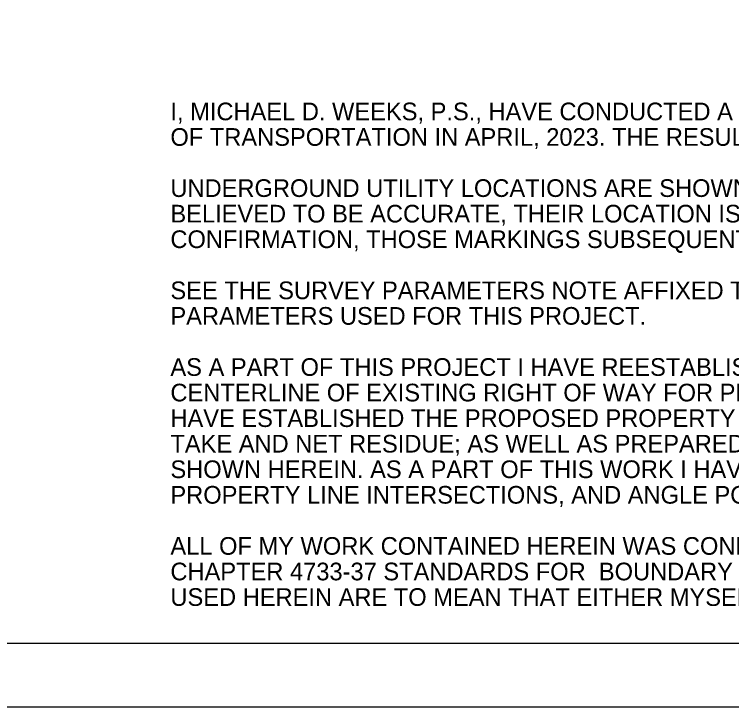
# Model space of a CAD drawing. Extents: x 0 to 34, y 0 to 22.
# Drawn here: x 16.3 to 21.98, y 0 to 5.49 of the extents above; entities that cross this region are included whole.
import ezdxf

# ---------------------------------------------------------------- set-up
doc = ezdxf.new("R2010")
doc.units = 0
for name, color, linetype in [('SH_Border', 7, 'Continuous'), ('SH_Cut_Line', 7, 'Continuous'), ('SH_Text', 7, 'Continuous')]:
    doc.layers.add(name, color=color, linetype=linetype)

msp = doc.modelspace()

# ---------------------------------------------------------------- linework, layer by layer
at = {"layer": 'SH_Border'}
msp.add_lwpolyline([(1.5, 21.5), (33.5, 21.5), (33.5, 0.5), (1.5, 0.5)], close=True, dxfattribs=at)
at = {"layer": 'SH_Cut_Line'}
msp.add_lwpolyline([(0, 0), (34, 0), (34, 22), (0, 22)], close=True, dxfattribs=at)

# ---------------------------------------------------------------- texts
at = {"layer": 'SH_Text'}
for s, p in [('I, MICHAEL D. WEEKS, P.S., HAVE CONDUCTED A SURVEY OF THE EXISTING CONDITIONS FOR THE OHIO DEPARTMENT ', (17.533, 4.646)), ('OF TRANSPORTATION IN APRIL, 2023. THE RESULTS OF THAT SURVEY ARE CONTAINED HEREIN.', (17.533, 4.4435)), ('UNDERGROUND UTILITY LOCATIONS ARE SHOWN FOR INFORMATIONAL PURPOSES ONLY. THOUGH THEY ARE ', (17.533, 4.0385)), ('BELIEVED TO BE ACCURATE, THEIR LOCATION IS AS MARKED ON THE GROUND BY THE UTILITY COMPANY PER OHIO811 ', (17.533, 3.836)), ('CONFIRMATION, THOSE MARKINGS SUBSEQUENTLY BEING SURVEYED AS A PART OF THIS PROJECT.', (17.533, 3.6335)), ('SEE THE SURVEY PARAMETERS NOTE AFFIXED TO THESE PLANS FOR THE HORIZONTAL AND VERTICAL SURVEY ', (17.533, 3.2285)), ('PARAMETERS USED FOR THIS PROJECT.', (17.533, 3.026)), ('AS A PART OF THIS PROJECT I HAVE REESTABLISHED THE LOCATIONS OF THE EXISTING PROPERTY LINES AND ', (17.533, 2.621)), ('CENTERLINE OF EXISTING RIGHT OF WAY FOR PROPERTY TAKES CONTAINED HEREIN. AS A PART OF THIS PROJECT I ', (17.533, 2.4185)), ('HAVE ESTABLISHED THE PROPOSED PROPERTY LINES, CALCULATED THE GROSS TAKE, PRESENT ROAD OCCUPIED, NET ', (17.533, 2.216)), ('TAKE AND NET RESIDUE; AS WELL AS PREPARED THE LEGAL DESCRIPTIONS NECESSARY TO ACQUIRE THE PARCELS ', (17.533, 2.0135)), ('SHOWN HEREIN. AS A PART OF THIS WORK I HAVE SET RIGHT OF WAY MONUMENTS AT PROPERTY CORNERS, ', (17.533, 1.811)), ('PROPERTY LINE INTERSECTIONS, AND ANGLE POINTS ON THE RIGHT OF WAY AS SHOWN HEREIN.', (17.533, 1.6085)), ('ALL OF MY WORK CONTAINED HEREIN WAS CONDUCTED IN ACCORDANCE WITH THE OHIO ADMINISTRATIVE CODE ', (17.533, 1.2035)), ('CHAPTER 4733-37 STANDARDS FOR  BOUNDARY SURVEYS, UNLESS NOTED OTHERWISE. THE WORDS "I" AND "MY" AS ', (17.533, 1.001)), ('USED HEREIN ARE TO MEAN THAT EITHER MYSELF OR SOMEONE WORKING UNDER MY DIRECT SUPERVISION.', (17.533, 0.7985))]:
    msp.add_text(s, height=0.14, rotation=360, dxfattribs=at).set_placement(p)

doc.saveas('drawing.dxf')
